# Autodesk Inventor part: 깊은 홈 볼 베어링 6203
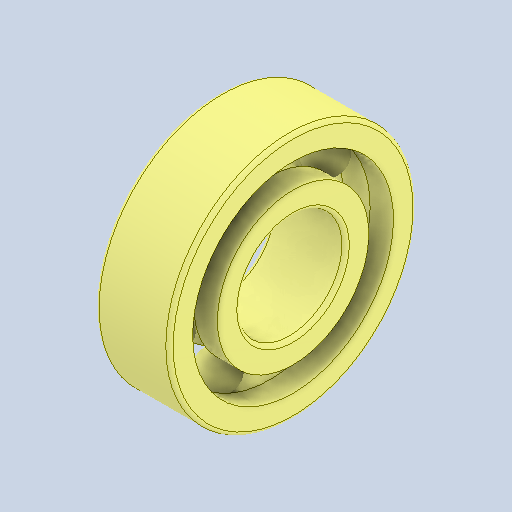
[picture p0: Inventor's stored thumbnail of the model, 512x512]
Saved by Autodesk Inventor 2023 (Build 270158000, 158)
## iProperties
Created: 2025-03
Part Number: 깊은 홈 볼 베어링 6203
Material: 강철, 연강
Description: 깊은 그루브 볼 베어링
Document SubType Name: Modeling
Designer: User
Density: 7.85 g/cm^3
Appearance: 기본값
Author: jhkim
Sending System: Autodesk Inventor 2025
Preprocessor: ST-DEVELOPER v20
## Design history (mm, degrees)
feature "Solid1"
feature "Solid1:1"
feature "Solid1:2"
feature "Solid1:3"
feature "Solid1:4"
feature "Solid1:5"
feature "Solid1:6"
feature "Solid1:7"
feature "Solid1:8"
node "솔리드1"
node "솔리드2"
node "솔리드3"
node "솔리드4"
node "솔리드5"
node "솔리드6"
node "솔리드7"
node "솔리드8"
node "솔리드9"
